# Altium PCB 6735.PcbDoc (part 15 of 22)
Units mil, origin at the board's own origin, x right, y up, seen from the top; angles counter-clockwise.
Board outline 2641.73 x 5165.35 mil, 6 copper layers (Top, Inner Layer 2, Inner Layer 3, Inner Layer 4, Inner Layer 5, Bottom), stack 35.7 mil thick; 1011 components, 790 nets, 4118 pads, 9325 vias.
Unrouted connection lines stored in the file: 4610.
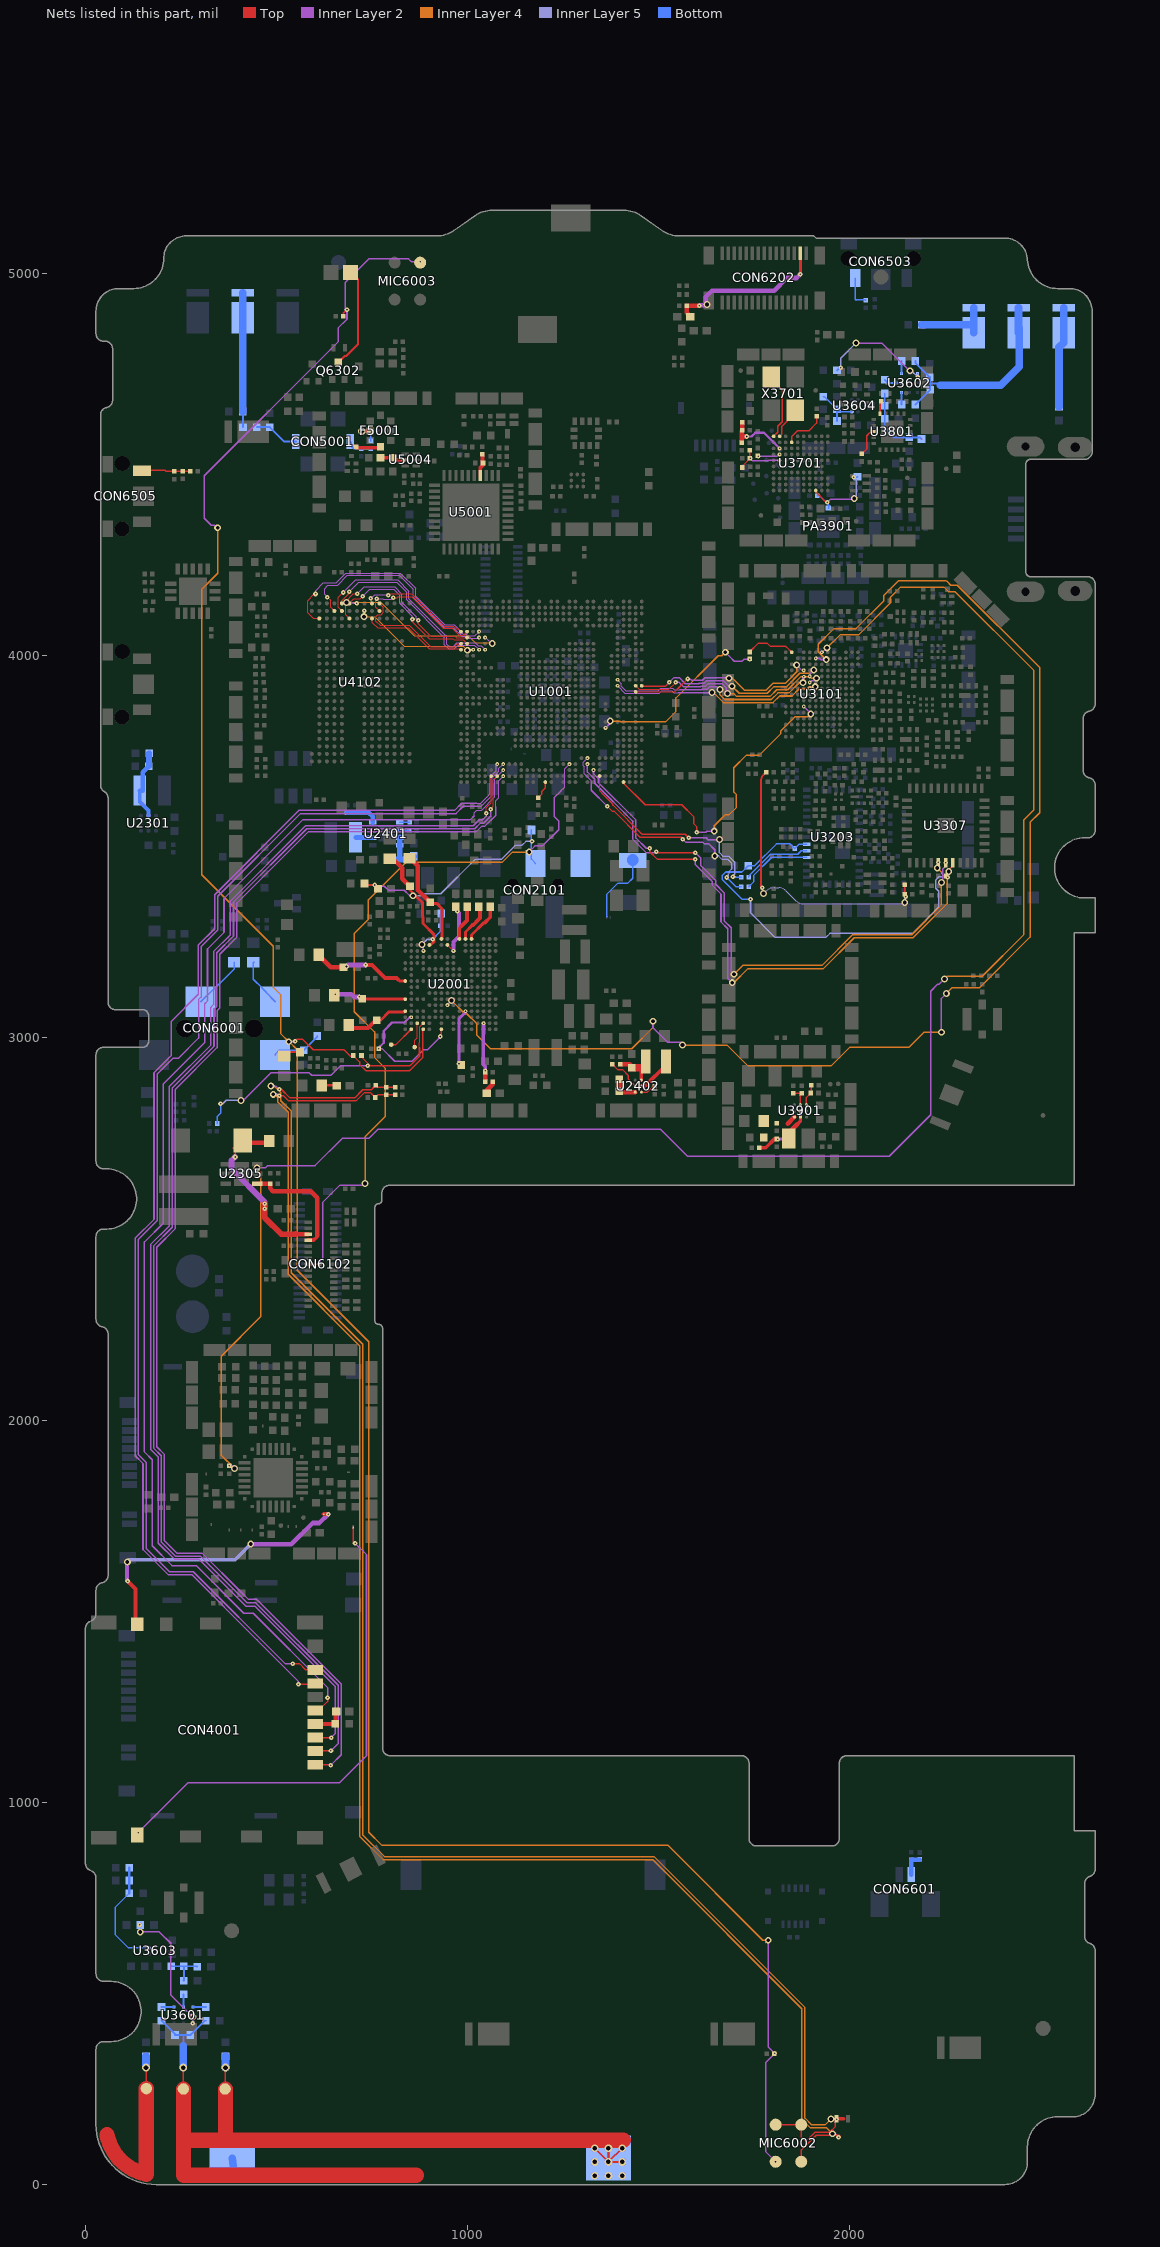
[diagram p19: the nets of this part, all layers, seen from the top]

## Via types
v1: diameter 12, hole 4, Top to Inner Layer 2, 3329 vias
v2: diameter 12, hole 4, Inner Layer 5 to Bottom, 3071 vias
v3: diameter 18, hole 10, Inner Layer 2 to Inner Layer 5, 1928 vias
v4: diameter 10, hole 4, Top to Inner Layer 2, 525 vias
v5: diameter 20, hole 12, Top to Bottom, 472 vias

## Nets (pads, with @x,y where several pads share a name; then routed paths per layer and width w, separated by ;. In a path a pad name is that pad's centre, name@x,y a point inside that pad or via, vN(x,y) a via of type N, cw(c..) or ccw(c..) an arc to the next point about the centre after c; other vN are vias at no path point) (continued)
LCM_LEDA: C2319.1 CON6102.3 D2301.2 | length 516.2
  Top w4: v1(391.35,2688.41) 391.35,2711.19 391.35,2731.15 D2301.2@411.31,2731.15 ; CON6102.3@581.19,2486.73 580.95,2486.97 CON6102.3@582.62,2486.73 581.31,2486.09 CON6102.3@581.95,2486.73
  Top w12: D2301.2@391.35,2711.19 D2301.2@411.31,2731.15 411.31,2725.89 476.53,2725.89 C2319.1@480.72,2730.09 ; 550.31,2486.73 581.19,2486.73 581.95,2486.73 CON6102.3@582.62,2486.73
  Top w15: v1(469.21,2553.49) v1@469.31,2553.49 ; v1(469.43,2565.59) 469.31,2565.59 v1@469.31,2553.49 ; 550.31,2486.73 549.67,2486.09 512.57,2486.09 469.31,2529.34 v1@469.31,2553.49
  Inner Layer 2 w15: v1(391.35,2688.41) 381.92,2678.98 381.92,2657.39 469.31,2570 v1@469.31,2567.09 ; v1(469.21,2553.49) 469.31,2554.79 v1@469.31,2567.09 ; v1(469.43,2565.59) v1@469.31,2567.09
LCM_LEDK: CON6102.4 R2310.1 U2305.1 | length 309
  Top w10: CON6102.4@582.62,2470.98 597.46,2470.98 606.31,2479.84 606.31,2481.91
  Top w12: U2305.1@449.29,2618.9 469.54,2618.9 469.95,2618.49 R2310.1@482.95,2618.49 482.95,2606.49 490.37,2599.07 589.44,2599.07 606.31,2582.2 606.31,2481.91
LCM_RST: CON6102.8 U1001.W4 | length 1910.4
  Top w4: CON6102.8@582.62,2407.99 599.34,2407.99 599.44,2408.09 v1(612.31,2408.09)
  Inner Layer 2 w3: 1243.95,3646.17 1253.45,3655.67 1253.45,3703.77 v4(1266.2,3716.51)
  Inner Layer 2 w4: v1(612.31,2408.09) 614.31,2408.09 614.31,2416.09 621.28,2423.06 621.28,2570.34 666.04,2615.09 731.65,2615.09 v3(731.65,2618.97) ; v3(1161.17,3486.23) 1161.17,3487.17 1169.5,3495.5 1177.1,3503.09 1196.49,3503.09 1238.31,3544.92 1238.31,3567.75 1225.95,3580.11 1225.95,3628.17 1243.95,3646.17
  Inner Layer 4 w4: v3(731.65,2618.97) 731.65,2741.43 783.95,2793.74 783.95,2921.07 756.31,2948.71 756.31,3015.72 703.31,3068.72 703.31,3273.08 739.31,3309.08 739.31,3360.3 838.1,3459.09 1089.83,3459.09 1116.97,3486.23 v3(1161.17,3486.23)
LTE_LTEX26M_IN: R1102.2 U3101.M1 | length 130.1
  Top w4: R1102.2@1738.15,4009.59 1738.15,4010.59 1760.64,4033.08 1783.37,4033.08 1791.13,4025.32 1830.81,4025.32 1833.54,4022.59 1834.15,4022.59 U3101.M1@1847.91,4008.83
LTE_RFIC0_BSI_CK: U1001.AG18 U3101.K6 | length 579.6
  Top w4: U3101.K6@1879.41,3930.09 1879.49,3930.09 1879.49,3944.92 v4(1879.58,3944.92)
  Inner Layer 2 w3: v4(1392.18,3936.99) 1402.07,3927.09 1402.07,3919.83 1413.34,3908.56 1498.78,3908.56 1504.81,3914.59 1536.45,3914.59 1540.46,3910.58 1555.02,3910.58 1555.27,3910.83
  Inner Layer 2 w4: 1555.27,3910.83 1611.86,3910.83 1612.64,3911.61 1625.68,3911.61 1632.66,3918.59 1652.51,3918.59 v3(1659.95,3911.15) ; v3(1877.14,3929.41) 1877.14,3942.49 v4(1879.58,3944.92)
  Inner Layer 4 w4: v3(1659.95,3911.15) 1659.95,3898.08 1672.62,3885.41 1794.45,3885.41 1811.62,3902.58 1840.68,3902.58 1867.51,3929.41 v3(1877.14,3929.41)
LTE_RFIC0_BSI_D0: U1001.AK17 U3101.J6 | length 558
  Top w3: U1001.AK17@1439.43,3921.24 1448.84,3911.81 1526.31,3911.81 1544.31,3929.81 v1(1544.31,3930.09)
  Inner Layer 2 w4: v1(1544.31,3930.09) 1553.69,3930.09 1564.95,3918.83 1608.51,3918.83 1609.3,3919.62 1622.1,3919.62 1629.07,3926.59 1665.73,3926.59 1676.68,3915.64 1676.68,3903.6 v3(1679.41,3900.88) ; v4(1895.16,3930.09) 1899.17,3934.1 1905.84,3934.1 v3(1912.68,3940.94)
  Inner Layer 4 w4: v3@1679.41,3900.83 1696.21,3900.83 1703.44,3893.61 1722.31,3893.61 1787.1,3893.59 1791.27,3893.6 1808.63,3910.96 1837.48,3910.96 1870.93,3944.41 1896.28,3944.41 1899.76,3940.94 v3(1912.68,3940.94)
LTE_RFIC0_BSI_D1: U1001.AL17 U3101.J5 | length 530.3
  Top w4: U1001.AL17@1455.17,3921.24 1455.17,3920.09 1517.31,3920.09 v1(1527.31,3930.09)
  Inner Layer 2 w4: v1(1527.31,3930.09) 1540.06,3942.83 1553.43,3942.83 1569.43,3926.83 1605.12,3926.83 1605.94,3927.65 1618.25,3927.65 1625.2,3934.59 1669.04,3934.59 1683.44,3920.19 v3(1691.68,3920.19) ; v4(1895.16,3945.83) 1895.16,3952.17 v3(1905.4,3962.41)
  Inner Layer 4 w4: v3(1691.68,3920.19) 1710.26,3901.61 1783.86,3901.61 1801.59,3919.34 1834.54,3919.34 1869.01,3953.81 1896.8,3953.81 v3(1905.4,3962.41)
LTE_RFIC0_BSI_D2: U1001.AK16 U3101.K4 | length 519.1
  Top w3: U1001.AK16@1439.43,3905.49 1541.71,3905.49 1548.31,3912.09
  Top w4: 1548.31,3912.09 v1(1575.31,3939.09)
  Inner Layer 2 w4: v1(1575.31,3939.09) 1575.31,3938.05 1583.31,3938.05 1586.2,3935.16 1602.47,3935.16 1603.01,3935.7 1613.87,3935.7 1620.77,3942.59 1682.25,3942.59 v3(1683.95,3940.89) ; v3(1860.81,3975.65) 1874.88,3961.58 v4(1879.41,3961.58)
  Inner Layer 4 w4: v3(1683.95,3940.89) 1682.65,3939.59 1694.12,3939.59 1724.1,3909.61 1780.5,3909.61 1799.05,3928.15 1831.2,3928.15 1860.81,3957.76 v3(1860.81,3975.65)
LTE_RFIC0_BSI_EN: U1001.AG17 U3101.J7 | length 574.6
  Inner Layer 2 w3: v4(1392.18,3921.24) 1411.05,3902.37 1501.59,3902.37 1507.81,3908.59 1533.97,3908.59 1539.73,3902.83 1551.62,3902.83
  Inner Layer 2 w4: 1551.62,3902.83 1615.21,3902.83 1615.98,3903.6 1621.86,3903.6 v3(1639.15,3903.59) ; v4(1895.16,3914.34) 1899.74,3918.92 v3@1909.4,3918.92
  Inner Layer 4 w4: v3(1639.15,3903.59) 1643.13,3903.59 1669.31,3877.41 1799.19,3877.41 1816.36,3894.58 1848.67,3894.58 1867.68,3913.59 1887.76,3913.59 1893.13,3918.96 v3(1909.43,3918.95) v3(1909.43,3918.95)
LTE_TXBPI: U1001.AH1 U3101.K10 | length 804.2
  Top w4: U1001.AH1@1407.93,3669.27 1407.93,3666.4 1464.44,3609.89 1560.26,3609.89 1590.95,3579.2 1590.95,3561.07 1598.95,3553.07 v1(1598.95,3537.88)
  Inner Layer 2 w4: v1(1598.95,3537.88) 1622.73,3537.88 1625.76,3540.9 v3(1645.12,3540.9) ; v4(1879.41,3867.09) 1879.31,3867 1898.19,3848.12 v3(1897.65,3847.59)
  Inner Layer 4 w4: v3(1645.12,3540.9) 1645.12,3555.09 1674.02,3583.99 1683.92,3583.99 1703.08,3603.15 1703.08,3636.64 1696.06,3643.66 1696.06,3706.74 1729.43,3740.11 1763.2,3740.11 1819.62,3796.53 1819.62,3803.4 1856.71,3840.49 1890.55,3840.49 v3(1897.65,3847.59)
LTE_VMIPI: C3241.1 C3340.2 R3278.2 U3203.7 U3307.7 | length 1142.8
  Top w4: C3340.2@2251.65,3423.59 2251.65,3420.59 v1(2255.65,3420.59) 2255.65,3436.69 2269.55,3450.59 U3307.7@2269.55,3458.15
  Inner Layer 2 w4: v1(2255.65,3420.59) 2255.65,3432.59 v3(2258.65,3435.59)
  Inner Layer 5 w4: v2(1740.02,3362.86) 1740.02,3327.51 1804.44,3263.09 1937.51,3263.09 1947.8,3273.38 2069.44,3273.38 2069.67,3273.61 2082.08,3273.61 2082.31,3273.38 2163.79,3273.38 2232.65,3342.24 2232.65,3383.47 2224.65,3391.47 2224.65,3412.8 2233.46,3421.61 2244.67,3421.61 v3(2258.65,3435.59)
  Bottom w4: R3278.2@1733.65,3450.59 R3278.2@1734.07,3450.59 ; v2(1740.02,3362.86) 1718.05,3362.86 1666.12,3414.8 1666.12,3424.74 1675.48,3434.1 1717.57,3434.1 R3278.2@1734.07,3450.59 ; U3203.7@1886.76,3506.89 1866.95,3506.89 C3241.1@1855.65,3495.59 1847.65,3503.59 1847.65,3504.08 1844.14,3507.59 1807.72,3507.59 1750.31,3450.17 1734.07,3450.17 R3278.2@1734.07,3450.59
LTE_VSRAM_EXT: C2412.1 L2402.2 R1011.1 U2402.C1 | length 157.9
  Top w10: U2402.C1@1454.19,2889.84 1454.19,2922.09 L2402.2@1454.19,2926.54 ; L2402.2@1454.19,2926.54 L2402.2@1465.74,2938.09 L2402.2@1454.19,2926.54
  Top w12: R1011.1@1399.31,2931.09 1424.31,2931.09 1429.31,2926.09 C2412.1@1429.31,2922.09
  Top w20: C2412.1@1429.31,2922.09 1454.19,2922.09 1465.74,2922.09 L2402.2@1465.74,2938.09
LTEX26M_IN: R1102.1 U1001.AE10 | length 500.3
  Top w4: U1001.AE10@1360.59,3811.09 v4(1360.69,3811) ; U1001.AE10@1360.59,3811.09 1360.31,3811.09 v4(1360.69,3811) ; U1001.AE10@1360.59,3811.09 v4(1360.69,3811) ; U1001.AE10@1360.59,3811.09 1360.77,3811.09 v4(1360.69,3811)
  Inner Layer 2 w4: v4(1360.69,3811) 1371.77,3822.09 1371.77,3829.34 1372.31,3829.88 v3(1373.08,3829.11) ; v3(1674.08,4009.11) 1685.26,3997.94 1685.26,3997.77 1697.44,3985.59 1717.65,3985.59 1722.65,3990.59 v1(1738.15,3990.59)
  Inner Layer 4 w4: v3(1373.08,3829.11) 1398.02,3829.11 1400.3,3826.83 1517.77,3826.83 1544.95,3854.01 1544.95,3889.67 1655.36,4000.08 1665.05,4000.08 v3(1674.08,4009.11)
MICBIAS0: C2042.1 C6012.1 C6038.1 MIC6002.1 MIC6003.1 U2001.N16 | length 6955.5
  Top w4: v1(548.31,2991.09) 553.31,2996.09 568.7,2996.09 595.96,2968.83 676.49,2968.83 693.83,2951.49 700.31,2951.49 C2042.1@700.31,2954.09 717.34,2937.06 717.34,2930.73 733.98,2914.09 847.64,2914.09 882.31,2948.77 882.31,3022.72 U2001.N16@884.09,3022.72 ; C6038.1@674.31,4888.09 674.31,4896.09 683.81,4905.59 v1(684.31,4905.09) ; MIC6003.1@875.78,5028.52 v1(875.78,5030.63) ; v1(1805.42,60.09) MIC6002.1@1805.85,59.66 ; C6012.1@1802.31,342.09 v1(1803.31,343.09) 1803.36,343.09 C6012.1@1802.31,342.09
  Inner Layer 2 w4: v3(345.95,4334.83) 345.09,4333.97 337.31,4341.75 336.66,4341.09 329.38,4341.09 310.95,4359.52 310.95,4470.99 637.31,4797.35 641.68,4801.72 ; v3(531.95,2989.83) 531.95,2990.46 548.31,2990.46 v1(548.31,2991.09) ; 637.34,4797.35 660.95,4820.96 660.95,4857.09 684.31,4880.45 v1(684.31,4905.09) 680.31,4905.09 680.31,4977.36 741.04,5038.09 845.31,5038.09 852.78,5030.63 v1(875.78,5030.63) ; v3(1786.31,639.09) 1786.31,505.09 1785.95,504.73 1785.95,360.45 v1(1803.31,343.09) 1780.31,320.09 1780.31,85.2 v1(1805.42,60.09)
  Inner Layer 4 w4: v3(345.95,4334.83) 345.95,4215.54 304.31,4173.9 304.31,3426.95 491.31,3239.95 491.31,3132.04 511.31,3112.04 511.31,3010.47 v3(531.95,2989.83) 532.73,2990.61 554.31,2969.02 554.31,2392.2 741.31,2205.2 741.31,921.46 774.69,888.09 1523.31,888.09 1772.31,639.09 v3(1786.31,639.09) v3@1780.47,633.25
MICBIAS1: C2044.1 R6011.2 U2001.N15 | length 762
  Top w3: 873.95,2973.87 873.95,2987.73 874.31,2988.09 874.31,3028.69 U2001.N15@884.09,3038.47
  Top w4: C2044.1@722.31,2954.09 723.31,2953.09 723.31,2949.09 v1@740.31,2932.09 ; v1(738.75,2927.09) 740.31,2927.09 v1@740.31,2932.09 ; 873.95,2973.87 873.95,2951.72 849.32,2927.09 745.31,2927.09 v1@740.31,2932.09
  Inner Layer 2 w4: v3(407.18,2835.9) 407.18,2837.18 413.37,2837.18 485.28,2909.09 585,2909.09 592,2902.09 642.2,2902.09 667.2,2927.09 v1(738.75,2927.09)
  Inner Layer 5 w4: v2(353.38,2827.79) 359.01,2827.79 368.4,2837.18 399.11,2837.18 v3(407.18,2835.9)
  Bottom w4: R6011.2@344.31,2776.09 344.31,2793.85 353.38,2802.92 v2(353.38,2827.79)
MIPI0_SCLK: R3209.2 U1001.AD2 | length 553.9
  Top w3: U1001.AD2@1344.94,3685.02 1344.94,3646.55 1350.6,3640.88
  Top w4: 1350.6,3640.88 1380.02,3611.46 1380.02,3609.1 1456.05,3533.07 1569.12,3533.07 v1(1578.67,3523.53)
  Inner Layer 2 w4: v1(1578.67,3523.53) 1624.27,3523.53 1629.09,3518.7 v3(1658.63,3518.7)
  Inner Layer 5 w4: v3(1658.63,3518.7) 1658.63,3485.13 1668.35,3475.41 1683.64,3475.41 1698.46,3460.59 1698.46,3428.57 1692.81,3422.92 v2(1694.12,3421.6)
  Bottom w4: v2(1694.12,3421.6) 1695.01,3420.71 1704.58,3420.71 1704.7,3420.59 R3209.2@1715.65,3420.59
MIPI0_SCLK_PA: R3209.1 U3203.6 | length 181.6
  Bottom w4: R3209.1@1735.65,3420.59 1735.65,3423.85 1791.39,3479.59 1792.32,3480.5 1834.97,3480.5 1835.06,3480.59 1863.54,3480.59 1872.51,3489.57 U3203.6@1886.76,3489.57
MIPI0_SDATA: R3210.2 U1001.AB5 | length 647.6
  Top w4: v1(1365.66,3605.78) 1378.96,3592.48 1383.81,3592.48 1451.23,3525.06 1559.41,3525.06 1564.29,3520.18 v1(1562.66,3520.18)
  Inner Layer 2 w3: v4(1313.44,3732.26) 1302.94,3721.76 1302.94,3711.99 1305.45,3709.48 1305.45,3690.9 1323.4,3672.95 1323.4,3670.19
  Inner Layer 2 w4: 1323.4,3670.19 1323.4,3648.03 v1(1365.66,3605.78) ; v1(1562.66,3520.18) 1571.32,3511.52 1583.82,3511.52 1584.79,3512.49 1614.4,3512.49 1618.5,3508.39 1630.18,3508.39 1646.35,3492.22 v3(1646.35,3476.2)
  Inner Layer 5 w4: v3(1646.35,3476.2) 1656.25,3476.2 1665.36,3467.09 1680.65,3467.09 1690.46,3457.28 1690.46,3441.94 1684.88,3436.36 1684.88,3431.74 1681.8,3428.66 1681.8,3425.37 1677.16,3420.72 v2(1678.12,3419.77)
  Bottom w4: v2(1678.12,3419.77) 1702.27,3395.59 R3210.2@1715.65,3395.59
MIPI0_SDATA_PA: R3210.1 U3203.5 | length 193
  Bottom w4: R3210.1@1735.65,3395.59 1748.15,3408.09 1748.15,3425.02 1795.63,3472.5 1886.5,3472.5 U3203.5@1886.76,3472.24
MIPI1_SCLK: U1001.AC3 U3307.5 | length 1539.7
  Top w4: v1(1476.22,3496.09) 1476.22,3487.31 1495.7,3467.83 v1(1594.95,3467.83) ; v1(2231.65,3459.59) 2231.76,3459.49 U3307.5@2231.76,3458.15
  Inner Layer 2 w4: v4(1329.19,3700.77) 1329.19,3691.65 1341.31,3679.53 1341.31,3668.84 1440.31,3569.84 1440.31,3522.77 1466.99,3496.09 v1(1476.22,3496.09) ; v1(1594.95,3467.83) 1594.95,3454.42 1639.51,3409.86 1639.51,3399.77 1662.79,3376.48 1662.79,3303.36 1680.69,3285.46 1680.69,3156.17 v3(1692.32,3144.54) ; v3(2228.65,3444.59) 2231.65,3447.59 v1(2231.65,3459.59)
  Inner Layer 4 w4: v3(1692.32,3144.54) 1696.33,3144.54 1733.35,3181.56 1930.73,3181.56 2011.17,3262 2164.97,3262 2254.65,3351.69 2254.65,3415.59 2240.04,3430.2 2240.04,3433.2 v3(2228.65,3444.59)
MIPI1_SDATA: U1001.AB4 U3307.6 | length 1524
  Top w4: v1(1493.78,3486.72) 1492.82,3485.77 1493.79,3484.8 v1(1594.95,3484.8) ; U3307.6@2250.65,3458.15 v1(2250.65,3458.59) ; U1001.AB4@1313.21,3716.74 v4(1313.44,3716.51) 1313.44,3716.97 U1001.AB4@1313.21,3716.74
  Inner Layer 2 w4: v4(1313.44,3716.51) 1313.44,3695.59 1332.31,3676.72 1332.31,3666.09 1432.31,3566.09 1432.31,3519.46 1467.68,3484.09 1491.14,3484.09 v1(1493.78,3486.72) ; v1(1594.95,3484.8) 1595.29,3485.14 1609.31,3471.12 1609.31,3451.55 1648.83,3412.03 1648.83,3401.79 1670.79,3379.83 1670.79,3306.67 1689.33,3288.13 1689.33,3202.98 1689.09,3202.74 1689.09,3190.32 1689.33,3190.08 1689.33,3173.5 1695.7,3167.13 1696.95,3167.13 v3(1696.95,3166.56) ; v3(2239.65,3406.59) 2243.54,3410.48 2243.54,3442.48 2250.65,3449.59 v1(2250.65,3458.59)
  Inner Layer 4 w4: v3(1696.95,3166.56) 1719.95,3189.56 1926.71,3189.56 2007.15,3270 2161.65,3270 2239.65,3348 v3(2239.65,3406.59)
MIPI_VRT: R1227.1 U1001.R1 | length 48
  Top w4: R1227.1@1184.95,3628.83 1193.24,3637.12 1193.24,3644.19 1203.2,3654.15 U1001.R1@1203.2,3669.27
MSDC0_CLK: U1001.C23 U4102.B8 | length 338
  Inner Layer 2 w3: v3(728.77,4102.14) 728.77,4115.97 v1(729.92,4117.11) ; v3(999.08,4014.11) 1000.69,4015.72 v4(1014.23,4015.73)
  Inner Layer 4 w3: v3(728.77,4102.14) 756.72,4102.14 834.25,4024.61 988.58,4024.61 v3(999.08,4014.11)
MSDC0_CMD: U1001.B24 U4102.A6 | length 404
  Top w3: U4102.A6@690.56,4136.8 702.42,4148.67 718.68,4148.67 v1(725.36,4155.35) ; v1(855.58,4094.86) 855.58,4088.86 899.83,4044.61 961.33,4044.61 964.86,4041.08 988.87,4041.08 U1001.B24@998.48,4031.47
  Inner Layer 2 w3: v1(725.36,4155.35) 744.29,4174.28 806.68,4174.28 822.15,4158.81 822.15,4136.72 855.58,4103.29 v1(855.58,4094.86)
MSDC0_DAT0: U1001.A26 U4102.A9 | length 298.3
  Top w3: v1(746.76,4149.89) 749.61,4147.03 U4102.A9@749.61,4136.8 ; v1(791.8,4157.78) 796.49,4162.47 853.22,4162.47 938.08,4077.61 962.83,4077.61 970.32,4070.11 975.58,4070.11 U1001.A26@982.73,4062.97
  Inner Layer 2 w3: v1(746.76,4149.89) 756.66,4159.79 789.78,4159.79 v1(791.8,4157.78)
MSDC0_DAT1: U1001.B26 U4102.B10 | length 323.7
  Top w3: v1(761.8,4149.29) 759.48,4146.97 759.48,4126.93 U4102.B10@769.3,4117.12 ; v1@806.3,4152.61 v1(805.65,4151.97) 815.59,4151.97 817.71,4154.09 853.12,4154.09 934.69,4072.52 934.8,4072.52 935.71,4071.61 959.63,4071.61 977.7,4053.55 989.06,4053.55 U1001.B26@998.48,4062.97
  Inner Layer 2 w3: v1(761.8,4149.29) 777.37,4149.29 779.38,4147.28 799.74,4147.28 v1(805.65,4151.97)
MSDC0_DAT2: U1001.B25 U4102.C6 | length 457.9
  Top w3: U4102.C6@690.56,4097.43 680.73,4107.25 680.73,4141.49 701.08,4161.84 v1(711.5,4161.84) ; v1(870.58,4092.22) 870.58,4083.37 903.34,4050.61 967.07,4050.61 970.45,4047.22 U1001.B25@998.48,4047.22
  Inner Layer 2 w3: v1(711.5,4161.84) 729.93,4180.28 809.17,4180.28 828.15,4161.29 828.15,4140.15 866.08,4102.22 866.08,4096.72 v1(870.58,4092.22)
MSDC0_DAT3: U1001.E23 U4102.B5 | length 549.9
  Top w3: U4102.B5@670.87,4117.12 661.05,4126.93 661.05,4152.32 v1(674.14,4165.42)
  Inner Layer 2 w3: v1(674.14,4165.42) 674.14,4165.86 706.55,4198.28 816.62,4198.28 846.15,4168.75 846.15,4148.47 945.62,4049 945.62,4030.47 952.48,4023.61 961.79,4023.61 971.79,4033.61 1020.09,4033.61 1027.48,4026.22 1035.22,4026.22 v4(1045.72,4015.73)
MSDC0_DAT4: U1001.A23 U4102.C9 | length 272.4
  Top w3: U4102.C9@749.61,4097.43 749.61,4088.11 764.61,4073.11 844.33,4073.11 899.83,4017.61 980.85,4017.61 U1001.A23@982.73,4015.73
MSDC0_DAT5: U1001.A24 U4102.A10 | length 316.9
  Top w3: U4102.A10@769.3,4136.8 779.11,4126.98 779.11,4113.05 773.34,4107.28 765.26,4107.28 759.47,4101.49 759.47,4090.47 770.83,4079.11 847.33,4079.11 902.83,4023.61 965.83,4023.61 973.33,4031.11 U1001.A24@982.33,4031.11
MSDC0_DAT6: U1001.D23 U4102.A5 | length 492.9
  Top w3: U4102.A5@670.87,4136.8 670.87,4143.7 690.38,4163.22 v1(690.38,4167.26)
  Inner Layer 2 w3: v1(690.38,4167.26) 715.4,4192.28 814.14,4192.28 840.15,4166.26 840.15,4145.99 938.91,4047.23 938.91,4028.69 950,4017.61 964.88,4017.61 974.88,4027.61 1017.61,4027.61 1025,4020.22 1029.74,4015.48 v4(1029.98,4015.73)
MSDC0_DAT7: U1001.D25 U4102.B4 | length 568.4
  Top w3: v1(633.14,4153.03) 641.37,4144.8 641.37,4126.93 U4102.B4@651.19,4117.12
  Inner Layer 2 w3: v1(633.14,4153.03) 625.52,4160.64 625.52,4175.77 634.15,4184.4 659.52,4184.4 685.4,4210.28 821.59,4210.28 858.15,4173.72 858.15,4153.44 938.49,4073.11 962.7,4073.11 985.2,4050.61 992.83,4050.61 997.33,4046.11 1028.87,4046.11 v4(1029.98,4047.22)
MSDC0_DSL: U1001.E25 U4102.A7 | length 483.7
  Inner Layer 2 w3: v3(682.6,4139.38) 696.63,4139.38 699.21,4136.8 v1(710.24,4136.8) ; v4(1045.72,4047.22) 1046.97,4047.22 1061.95,4032.24 1064.31,4032.24 v3(1064.31,4032.09)
  Inner Layer 4 w3: v3(682.6,4139.38) 772.83,4139.38 860.31,4051.9 1001.49,4051.9 1019.28,4034.11 1064.08,4034.11 1064.11,4032.92 1064.45,4032.86 1065.32,4032.71 1065.91,4032.59 1066.04,4032.57 v3(1064.31,4032.09)
MSDC0_RSTB: U1001.D26 U4102.C2 | length 636.9
  Top w3: v1(601.95,4161.49) 598.92,4161.49 580.95,4143.52 580.95,4112.49 595.94,4097.5 U4102.C2@611.82,4097.43
  Inner Layer 2 w3: v1(601.95,4161.49) 601.95,4170.49 621.86,4190.4 655.66,4190.4 681.54,4216.28 824.1,4216.28 864.15,4176.22 864.15,4155.93 939.47,4080.61 964.33,4080.61 988.33,4056.61 995.83,4056.61 1000.33,4052.11 1019.12,4052.11 v4(1029.98,4062.97)
MSDC1_CLK: CON4001.5 U1001.H3 | length 3384.4
  Top w4: CON4001.5@601.19,1240.23 610,1240.23 633.31,1263.55 v1(633.31,1273.09)
  Inner Layer 2 w3: 1017.31,3581.26 1017.31,3589.09 1024.31,3596.09 1036.31,3596.09 1070.94,3630.72 1070.94,3677.95 1093.36,3700.37 v4(1092.97,3700.77) v4@1090.95,3698.75
  Inner Layer 2 w4: v1(633.31,1273.09) 633.31,1300.37 438.92,1494.76 414.44,1494.76 289.62,1619.58 226.36,1619.58 174.51,1671.43 174.51,1896.5 154.31,1916.7 154.31,2465.99 203.31,2514.99 203.31,2879.46 312.03,2988.18 312.03,3089.44 319.31,3096.72 319.31,3232.84 362.46,3275.99 362.46,3364.45 569.11,3571.09 1007.14,3571.09 1017.31,3581.26
MSDC1_CMD: CON4001.3 U1001.F2 | length 3446.3
  Top w3: v1(1048.17,3587.63) 1048.17,3602.38 1061.47,3615.68 U1001.F2@1061.47,3685.02
  Top w4: CON4001.3@601.19,1169.37 602.91,1171.09 607.31,1171.09 609.31,1169.09 v1(642.6,1169.09)
  Inner Layer 2 w4: v1(642.6,1169.09) 653.31,1179.8 653.31,1302.99 443.44,1512.87 420.3,1512.87 297.34,1635.83 232.73,1635.83 190.51,1678.05 190.51,1903.31 170.31,1923.51 170.31,2459.17 219.31,2508.17 219.31,2872.62 328.12,2981.43 328.12,3080.35 335.31,3087.54 335.31,3226.13 379.2,3270.02 379.2,3358.55 575.73,3555.09 1014.81,3555.09 1030.3,3570.58 1039.12,3570.58 1048.17,3579.63 v1(1048.17,3587.63)
MSDC1_DAT0: CON4001.7 U1001.G4 | length 3324.8
  Top w4: v1(557.31,1309.09) 599.18,1309.09 CON4001.7@601.19,1311.1
  Inner Layer 2 w3: 1023.31,3614.09 1033.73,3614.09 1058.52,3638.88 1058.52,3682.93 1074.95,3699.36 1074.95,3714.24 v4(1077.22,3716.51)
  Inner Layer 2 w4: v1(557.31,1309.09) 557.31,1316.37 448.8,1424.88 278.52,1595.17 245.39,1595.17 245.31,1595.09 216.91,1595.09 150.51,1661.48 150.51,1886.29 130.31,1906.49 130.31,2476.22 179.31,2525.22 179.31,2909.09 224.22,2954 224.22,3029.61 224.31,3029.71 224.31,3043.09 295.31,3114.09 295.31,3242.84 338,3285.53 338,3374.77 558.33,3595.09 965.31,3595.09 984.31,3614.09 1023.31,3614.09
MSDC1_DAT1: CON4001.8 U1001.H4 | length 3306.1
  Top w4: v1(542.31,1363.09) 559.68,1363.09 576.23,1346.53 CON4001.8@601.19,1346.53 ; v4(1092.97,3716.51) 1093.93,3716.51 v4(1092.97,3716.51)
  Inner Layer 2 w3: 1027.31,3606.09 1035.31,3606.09 1064.61,3635.39 1064.61,3680.21 1081.95,3697.55 1081.95,3705.49 v4(1092.97,3716.51)
  Inner Layer 2 w4: v1(542.31,1363.09) 522.41,1363.09 282.18,1603.31 220,1603.31 158.51,1664.8 158.51,1889.69 138.31,1909.89 138.31,2472.81 187.31,2521.81 187.31,2905.09 229.23,2947 243.31,2947 295.8,2999.49 295.8,3100.46 303.31,3107.97 303.31,3239.52 346.15,3282.36 346.15,3370.76 562.48,3587.09 969.63,3587.09 988.63,3606.09 1027.31,3606.09
MSDC1_DAT2: CON4001.1 U1001.H2 | length 3536.3
  Top w4: v1@643.22,1097.49 v1(642.23,1097.49) 641.22,1098.5 CON4001.1@601.19,1098.5 ; CON4001.1@601.19,1098.5 603.19,1096.49 CON4001.1@601.19,1098.5
  Inner Layer 2 w3: 1073.31,3604.27 1073.31,3621.09 1081.06,3628.84 1081.06,3673.1 v4(1092.97,3685.02)
  Inner Layer 2 w4: v1(642.23,1097.49) 669.31,1124.57 669.31,1309.63 448.11,1530.83 426.48,1530.83 406.22,1551.09 305.23,1652.09 239.1,1652.09 206.51,1684.68 206.51,1910.13 186.31,1930.33 186.31,2452.34 235.31,2501.34 235.31,2865.95 344.31,2974.95 344.31,3071.33 351.31,3078.33 351.31,3219.15 396.31,3264.15 396.31,3353.04 582.36,3539.09 1022.14,3539.09 1037.14,3554.09 1045.26,3554.09 1073.31,3582.15 1073.31,3604.27
MSDC1_DAT3: CON4001.2 U1001.G2 | length 3487.8
  Top w3: v1@1059.95,3598.28 v1(1060.24,3598.28) 1067.47,3605.51 1067.47,3675.27 U1001.G2@1077.22,3685.02
  Top w4: CON4001.2@601.19,1133.93 CON4001.2@602.34,1135.09 ; CON4001.2@603.74,1136.49 CON4001.2@602.34,1135.09 ; v1(642.31,1135.09) CON4001.2@602.34,1135.09
  Inner Layer 2 w4: v1(642.31,1135.09) 661.31,1154.09 661.31,1306.31 445.77,1521.85 423.39,1521.85 301.28,1643.96 235.92,1643.96 198.51,1681.37 198.51,1906.72 178.31,1926.92 178.31,2455.76 227.31,2504.76 227.31,2869.28 336.31,2978.28 336.31,3075.94 343.31,3082.94 343.31,3222.64 387.31,3266.64 387.31,3355.36 579.05,3547.09 1018.48,3547.09 1033.48,3562.09 1041.94,3562.09 1060.24,3580.38 v1(1060.24,3598.28)
MSDC_NFC_SWPIO: CON4001.9 SH5108.1 | length 1299.7
  Top w4: CON4001.9@135.64,914.44 135.63,918.51 v1(137.95,920.83) ; SH5108.1@700.31,1719.09 700.31,1683.09 v1(705.31,1678.09)
  Inner Layer 2 w4: v1(137.95,920.83) 267.75,1050.63 664.15,1050.63 735.31,1121.79 735.31,1648.09 v1(705.31,1678.09)
MSDC_NFC_VCCSWP: CON4001.10 SH5107.1 | length 765.6
  Top w10: v1(110.15,1579.03) 131.31,1557.87 131.31,1469.94 CON4001.10@135.64,1465.63 ; SH5107.1@623.3,1754.09 634.38,1754.09 v1(634.78,1753.69)
  Inner Layer 2 w10: v3(109.54,1629.06) 108.31,1629.06 108.31,1579.03 v1(110.15,1579.03)
  Inner Layer 2 w12: v3(432.34,1675.49) 538.84,1675.49 594.18,1730.83 611.93,1730.83 v1(634.78,1753.69)
  Inner Layer 5 w10: v3(109.54,1629.06) 115.31,1634.83 391.68,1634.83 v3(432.34,1675.49)
MT6169_XO3_CLK: R5130.1 U3101.G1 | length 4799.5
  Inner Layer 2 w4: v1(376.31,1880.09) 384.31,1880.09 390.31,1874.09 v3(390.31,1873.09) ; v3(448.55,2660.09) 470.8,2660.09 476.8,2666.09 600.91,2666.09 671.91,2737.09 741.22,2737.09 765.22,2761.09 1504.31,2761.09 1574.84,2690.56 2102.99,2690.56 2211.31,2798.88 2211.31,3122.15 2229.34,3140.17 2233.4,3140.17 v3(2247.31,3154.09) ; v4(1926.65,4008.83) 1927.14,4008.34 1939.88,4021.08 v3(1940.36,4020.59)
  Inner Layer 4 w4: v3(390.31,1873.09) 355.31,1908.09 355.31,2167.4 458.31,2270.4 458.31,2650.32 v3(448.55,2660.09) ; v3(1940.36,4020.59) 1974.27,4054.5 2022.27,4054.5 2106.06,4138.3 2106.06,4152.8 2132.77,4179.5 2246.18,4179.5 2247.18,4178.5 2247.28,4178.5 2258.21,4167.57 2275.33,4167.57 2480.65,3962.24 2480.65,3595.93 2455.4,3570.68 2455.4,3437.62 ; v3(2247.31,3154.09) 2254.31,3161.09 2346.15,3161.09 2455.43,3270.37 2455.43,3376.38 ; 2455.41,3376.4 2455.41,3437.61
MT6169_XO4_CLK: U2001.J12 U3101.H2 | length 3437.5
  Inner Layer 2 w4: v4(947.08,3085.71) 946.58,3086.22 957.95,3097.58 v3(957.44,3098.09) ; v3(1484.72,3043.56) 1484.72,3026.83 1523.46,2988.09 1558.31,2988.09 1562.26,2987.91 1562.31,2987.23 v3(1562.3,2981.36) ; v4(1910.9,3993.08) 1920.79,3993.08 1924.28,3989.59 v3(1938.16,3989.59) ; v3(2239.38,3014.91) 2239.38,3103.15 v3(2252.31,3116.09)
  Inner Layer 4 w4: v3(957.44,3098.09) 992.37,3063.16 997.84,3063.16 1024.13,3036.86 1024.13,3007.14 1059.44,2971.83 1429.27,2971.83 1484.72,3027.29 v3(1484.72,3043.56) ; v3(1562.3,2981.36) 1678.78,2981.36 1733.57,2926.56 1950.73,2926.56 1999.26,2975.09 2153.99,2975.09 2193.81,3014.91 v3(2239.38,3014.91) ; v3(1938.16,3989.59) 1917.36,4010.38 1917.36,4030.12 1958.17,4070.92 2016.06,4070.92 2089.06,4143.92 2089.06,4158.42 2126.29,4195.65 2252.65,4195.65 2253.8,4194.5 2253.9,4194.5 2263.86,4184.54 2280.98,4184.54 2496.65,3968.87 2496.65,3589.3 2471.4,3564.05 2471.4,3465.98 2471.41,3383.09 ; v3(2252.31,3116.09) 2267.31,3131.09 2338.78,3131.09 2471.43,3263.74 2471.43,3383.07
N814026: CON6001.5 R6002.2 R6005.1 | length 133.1
  Bottom w4: CON6001.5@496.24,2954.83 498.24,2959.09 506.64,2967.49 R6005.1@570.95,2967.49 606.31,3002.85 R6002.2@606.31,3005.09
N814140: BEAD6003.2 CON6001.4 | length 129.6
  Bottom w4: BEAD6003.2@438.95,3197.9 440.95,3197.9 438.95,3195.9 438.95,3153.37 449.36,3142.96 449.87,3142.96 CON6001.4@496.24,3094.59
N814198: BEAD6005.2 CON6001.3 | length 140.5
  Bottom w4: CON6001.3@301.36,3094.59 364.89,3156.12 365.38,3156.12 388.95,3179.69 BEAD6005.2@388.95,3197.9
N814232: BEAD6002.1 R6003.2 | length 53.6
  Top w4: R6003.2@559.57,2964.83 561.31,2963.09 R6003.2@561.31,2962.09
  Top w6: BEAD6002.1@519.95,2952.42 519.95,2959.83 523.21,2963.09 R6003.2@561.31,2963.09
N814252: BEAD6004.1 R6004.2 | length 39.4
  Top w6: BEAD6004.1@618.54,2875.83 655.95,2875.83 655.95,2874.83 R6004.2@656.95,2874.83
N816374: C6013.2 C6016.1 MIC6002.4 R6023.1 | length 4284.9
  Top w4: v1(506.95,2848.83) 517.85,2848.83 531.59,2835.09 707.95,2835.09 728.95,2856.09 746.8,2856.09 750.31,2852.57 750.31,2852.09 C6016.1@758.31,2844.09 765.31,2851.09 C6013.2@787.31,2851.09 R6023.1@810.31,2851.09 ; MIC6002.4@1872.78,59.66 1872.78,90.09 1911.78,129.09 1973.31,129.09 1973.31,122.81 1972.03,124.09 v1(1970.31,124.09)
  Inner Layer 2 w4: v3(491.46,2852.38) 503.4,2852.38 v1(506.95,2848.83) ; v3(1954.94,132.75) 1961.66,132.75 v1(1970.31,124.09)
  Inner Layer 4 w4: v3(491.46,2852.38) 495.41,2852.38 503.14,2844.65 503.14,2832.41 530.31,2805.24 530.31,2381.85 717.31,2194.85 717.31,911.52 778.75,850.09 1483.94,850.09 1874.31,459.71 1874.31,170.78 1897,148.09 1939.6,148.09 v3(1954.94,132.75)
N816382: C6013.1 C6015.1 MIC6002.2 MIC6002.3 R6024.1 SH6003.1 | length 4382.3
  Top w4: v1(506.95,2865.83) 506.76,2865.64 512.35,2865.64 534.9,2843.09 704.58,2843.09 725.58,2864.09 747.8,2864.09 751.61,2867.89 751.61,2868.38 C6015.1@759.31,2876.09 764.31,2871.09 C6013.1@787.31,2871.09 R6024.1@810.31,2871.09 ; MIC6002.2@1805.85,156.52 MIC6002.3@1872.78,156.52 1872.78,123.63 1881.31,115.09 1886.46,115.09 1908.46,137.09 1947.31,137.09 1962.31,152.09 1962.31,169.09 SH6003.1@1965.31,172.09 v1(1965.31,171.09)
  Inner Layer 2 w4: v3(484.96,2874.09) 498.69,2874.09 v1(506.95,2865.83) ; v3(1950.25,171.71) 1950.31,171.65 1950.31,170.09 1951.31,171.09 v1(1965.31,171.09)
  Inner Layer 4 w4: v3(484.96,2874.09) 484.96,2872.09 495.96,2872.09 511.14,2856.9 511.14,2835.72 538.31,2808.55 538.31,2385.3 725.31,2198.3 725.31,914.83 782.06,858.09 1487.26,858.09 1882.31,463.03 1882.31,174.09 1900.31,156.09 1934.63,156.09 v3(1950.25,171.71)
N15601288: R2041.2 U2001.F1 | length 111.5
  Top w8: U2001.F1@994.32,3258.94 994.32,3270.2 994.32,3277.2 1012.95,3295.83
  Top w10: 1012.95,3295.83 1014.46,3295.83 1028.31,3309.7 1028.31,3309.92 1032.31,3313.92 1032.31,3341.83 R2041.2@1028.95,3341.83 ; R2041.2@1023.95,3341.83 R2041.2@1028.45,3341.83 ; R2041.2@1028.95,3342.83 R2041.2@1028.45,3341.83 ; R2041.2@1028.45,3341.83 1027.95,3340.83 R2041.2@1028.95,3341.83 ; R2041.2@1028.45,3341.83 R2041.2@1028.95,3341.83
N15601296: R2040.2 U2001.E1 | length 105.6
  Top w8: U2001.E1@1010.07,3258.94 1010.07,3269.4 1041.76,3301.09 1044.31,3301.09
  Top w10: 1044.31,3301.09 1058.95,3315.73 R2040.2@1058.95,3342.83
N15601786: R2046.2 U2001.G1 | length 102
  Top w4: R2046.2@993.59,3342.23 998.55,3342.23 998.95,3341.83 R2046.2@998.95,3342.83
  Top w8: U2001.G1@978.57,3258.94 978.57,3273.88 978.57,3287.45 982.95,3291.83
  Top w10: 982.95,3291.83 997.95,3306.83 997.95,3336.83 R2046.2@998.95,3341.83 ; R2046.2@995.95,3341.83 R2046.2@998.95,3341.83 ; R2046.2@997.95,3340.83 R2046.2@998.95,3341.83
N15603707: TP2016.1 U2001.P15 | length 65.3
  Top w3: TP2016.1@861.31,2976.09 861.31,2993.74 868.31,3000.74 868.31,3031.6 ; 868.34,3031.63 U2001.P15@868.34,3038.47
N15603711: TP2015.1 U2001.R16 | length 69.3
  Top w4: TP2015.1@800,2982.5 812.37,2982.5 U2001.R16@852.59,3022.72
N15605292: C2027.1 U2001.F13 | length 153.4
  Top w4: v1(977.31,2932.49) 977.96,2933.14 982.66,2928.44 982.66,2929.09 C2027.1@983.31,2929.09
  Inner Layer 2 w8: v1(977.31,2932.49) 977.31,3050.24 994.32,3067.25 v4(994.32,3069.96)
N15606290: C2036.1 U2001.K16 U2001.R14 | length 367
  Top w4: C2036.1@766.31,2973.09 v1(767.31,2972.09) ; v1(928.21,3003.66) 930.3,3008.09 v1@931.3,3008.09 ; v1@931.33,3008.11 U2001.K16@931.33,3022.72 ; U2001.K16@932.3,3022.09 U2001.K16@931.67,3022.72 ; U2001.K16@931.33,3022.72 U2001.K16@931.67,3022.72 ; U2001.K16@931.33,3022.72 U2001.K16@931.67,3022.72
  Inner Layer 2 w4: v1@765.31,2972.09 v1(767.31,2972.09) 776.16,2972.09 809.16,2939.09 854.17,2939.09 884.17,2969.09 894.85,2969.09 928.21,3002.45 v1(928.21,3003.66)
  Inner Layer 2 w6: v1@765.31,2972.09 780.31,2987.09 780.31,3018.09 802.31,3040.09 834.31,3040.09 848.44,3054.22 v4(852.59,3054.22)
N15921668: ANT3605.1 ANT3605.2 R3622.1 | length 263.7
  Bottom w20: R3622.1@2546.95,4651.49 2546.95,4806.73 2559.31,4819.09 ANT3605.2@2559.31,4845.13 ANT3605.1@2559.31,4910.09
N15925478: ANT3604.1 ANT3604.2 L3602.1 L3608.2 R3606.2 R3611.1 R3614.1 | length 583.8
  Bottom w5: R3606.2@2171.3,4657.09 L3602.1@2210.3,4696.09 2210.3,4712.09 ; L3608.2@2171.3,4771.09 2171.3,4767.09 2209.3,4729.09 R3614.1@2209.3,4728.09 2210.3,4728.09 2210.3,4712.09 ; 2236.3,4708.09 2236.3,4712.09 2210.3,4712.09
  Bottom w19.69: 2236.3,4708.09 2395.3,4708.09 2443.3,4756.09 2443.3,4793.09
  Bottom w20: ANT3604.1@2441.31,4910.09 ANT3604.2@2441.31,4845.13 2443.3,4858.05 2443.3,4793.09
N16931615: ANT5003.1 ANT5003.2 C5003.1 R5004.1 | length 359.8
  Bottom w4: C5003.1@410.96,4647.09 410.96,4639.09 C5003.1@411.31,4639.09
  Bottom w5: C5003.1@411.31,4639.09 412.31,4638.09 R5004.1@412.31,4598.09
  Bottom w20: C5003.1@411.31,4639.09 ANT5003.2@411.31,4884.13 ANT5003.1@411.31,4949.09
N16931617: CON5001.2 L5011.1 R5005.1 | length 66.8
  Bottom w5: CON5001.2@692.17,4560.09 695.31,4556.95 695.31,4548.09 701.31,4542.09 L5011.1@721.31,4542.09 R5005.1@746.31,4542.09
N16931618: CON5001.1 L5004.1 R5004.2 | length 117.9
  Bottom w5: R5004.2@448.31,4598.09 L5004.1@482.31,4598.09 520.31,4560.09 CON5001.1@550.43,4560.09
N16931625: F5001.2 L5012.1 R5005.2 | length 71.1
  Top w10: v5(723.31,4587.09) 745.38,4587.09 F5001.2@745.38,4588.11
  Bottom w5: v5(723.31,4587.09) L5012.1@746.31,4587.09 R5005.2@746.31,4562.09
N16931626: C5004.1 F5001.4 | length 69.6
  Top w10: C5004.1@708.08,4547.11 708.08,4544.09 771.95,4544.09 F5001.4@771.95,4546.77
N17415034: L5010.1 R5016.2 U5001.34 | length 60.2
  Top w10: U5001.34@1032.7,4471.17 1032.7,4491.53 1040.08,4498.91 L5010.1@1040.08,4504.11 1039.1,4505.09 1039.1,4527.09 R5016.2@1038.31,4527.09
N17416996: C5017.1 L5003.2 U5004.5 | length 67.7
  Top w10: L5003.2@772.08,4518.11 C5017.1@804.08,4518.11 810.08,4512.11 U5004.5@837.3,4512.11
N17645327: C6601.1 CON6601.1 R6601.2 | length 61.3
  Bottom w12: CON6601.1@2160.7,810.83 2160.95,810.83 C6601.1@2160.95,849.83 R6601.2@2182.95,849.83
N17960953: CON2101.3 R2137.1 R2139.2 | length 192.2
  Bottom w4: R2139.2@1363.31,3317.09 1363.31,3375.09 1392.31,3404.09 1418.31,3404.09 1431.95,3417.72 R2137.1@1431.95,3464.61
  Bottom w30: R2137.1@1431.95,3464.61 R2137.1@1431.95,3465.6
N18046092: C2019.1 R2037.2 U2001.T11 | length 209.6
  Top w4: R2037.2@650.54,3111.83 650.54,3114.09 v1(653.31,3114.09) ; v1(716.31,3107.09) 719.31,3107.09 C2019.1@724.31,3102.09 ; C2019.1@722.31,3098.59 722.31,3097.09 721.56,3097.84 C2019.1@722.31,3098.59 ; C2019.1@722.31,3098.59 725.06,3101.34 724.31,3101.34 C2019.1@724.31,3102.09 ; C2019.1@722.31,3098.59 722.31,3102.09 C2019.1@724.31,3102.09
  Top w8: C2019.1@724.31,3102.09 837.47,3102.09 U2001.T11@836.84,3101.46
  Inner Layer 2 w12: v1(653.31,3114.09) 695.93,3114.09 702.93,3107.09 v1(716.31,3107.09)
N18046094: C2016.1 R2036.2 U2001.K1 | length 258.2
  Top w4: U2001.K1@931.33,3258.94 931.58,3258.94 U2001.K1@932.31,3259.68
  Top w8: C2016.1@901.95,3354.83 901.95,3352.18 918.95,3352.18 932.31,3338.82 U2001.K1@932.31,3259.68
  Top w12: R2036.2@847.95,3469.9 849.95,3469.9 868.95,3450.9 868.95,3386.83 869.95,3386.83 C2016.1@901.95,3354.83
N18046114: C2017.1 R2099.2 U2001.T8 | length 262.9
  Top w4: C2017.1@675.31,3183.09 C2017.1@675.31,3185.09 677.05,3186.83 v1(682.95,3186.83)
  Top w8: 817.95,3152.83 822.08,3148.7 U2001.T8@836.84,3148.7
  Top w10: v1(732.95,3190.83) 749.38,3190.83 783.38,3156.83 813.95,3156.83 817.95,3152.83
  Top w12: R2099.2@610.54,3217.83 610.54,3215.83 641.28,3185.09 C2017.1@675.31,3185.09
  Inner Layer 2 w12: v1(682.95,3186.83) 686.95,3190.83 v1(732.95,3190.83)
N18046118: C2018.1 R2098.2 U2001.T13 | length 175.1
  Top w8: C2018.1@761.95,3045.83 761.95,3047.09 773.33,3047.09 794.33,3068.09 834.97,3068.09 U2001.T13@836.84,3069.96
  Top w10: R2098.2@688.9,3033.83 689.54,3025.83 739.03,3025.83 760.49,3047.29 761.95,3047.29 C2018.1@761.95,3047.09
N18047216: C2020.1 R2047.2 U2001.M2 | length 297.4
  Top w8: C2020.1@848.95,3396.49 848.95,3386.83 881.95,3353.83 881.95,3316.88 882.95,3315.88 882.95,3299.17 912.31,3269.81 912.31,3252.79 902.71,3243.19 U2001.M2@899.83,3243.19
  Top w12: R2047.2@796.31,3468.5 796.31,3477.09 828.95,3444.45 828.95,3416.49 C2020.1@848.95,3396.49
N18144801: C2403.1 R2405.2 U2402.A2 | length 74.9
  Top w12: C2403.1@1396.31,2860.09 1398.06,2858.34 U2402.A2@1438.44,2858.34
  Top w20: C2403.1@1396.31,2860.09 R2405.2@1396.31,2892.09
N18144815: R2404.2 U2402.B2 | length 89.2
  Top w4: R2404.2@1378.31,2931.09 1392.31,2917.09 1404.8,2917.09 1420.31,2901.57 1420.31,2892.22 U2402.B2@1438.44,2874.09
N18144862: R2407.2 U2402.A1 | length 41.2
  Top w4: U2402.A1@1454.19,2858.34 1469.57,2858.34 1484.31,2873.09 R2407.2@1489.31,2873.09
N18144873: L2402.1 U2402.B1 | length 96.8
  Top w10: U2402.B1@1454.19,2874.09 1464.36,2874.09 1518.89,2928.62 L2402.1@1518.89,2938.09
N18144932: R2403.2 U2401.5 | length 26.4
  Bottom w4: U2401.5@821.98,3563.64 835.87,3563.64 836.34,3564.11 R2403.2@848.2,3564.11
N18144946: C2402.1 R2408.2 U2401.7 U2401.8 | length 129.6
  Bottom w15: C2402.1@792.31,3467.09 818.31,3467.09 ; U2401.7@821.98,3524.27 U2401.8@821.98,3504.58 821.98,3470.75 818.31,3467.09 ; R2408.2@859.31,3475.09 859.31,3474.09 852.31,3467.09 818.31,3467.09
N18144981: R2406.2 U2401.6 | length 25.6
  Bottom w4: U2401.6@821.98,3543.95 836.09,3543.95 836.93,3543.11 R2406.2@847.2,3543.11
N18263809: C3334.1 R3327.1 R3334.2 | length 766.4
  Top w5: v1(1770.65,3392.59) 1769.77,3393.47 cw(c1774.9,3398.59) 1767.65,3398.59 1767.65,3671.59 cw(c1794.21,3671.59) C3334.1@1775.42,3690.36 ; C3334.1@1775.43,3690.37 C3334.1@1780.65,3695.59 ; R3334.2@2143.65,3400.59 R3327.1@2143.65,3375.59 2145.84,3375.59 v1(2145.84,3369.73)
  Inner Layer 2 w3: v1(1770.65,3392.59) 1770.65,3380.59 v3(1773.65,3377.59) ; v3(2143.65,3354.59) 2144.75,3354.59 2144.75,3369.73 v1(2145.84,3369.73)
  Inner Layer 5 w3: v3(1773.65,3377.59) 1779.46,3383.4 cw(c1801.65,3361.21) 1801.65,3392.59 1813.65,3392.59 cw(c1813.65,3365.96) 1832.48,3384.79 1858.92,3358.35 ccw(c1877.65,3377.08) 1877.65,3350.59 2139.65,3350.59 v3(2143.65,3354.59)
N18274814: CON6505.2 R6508.2 R6509.2 R6510.2 | length 129.8
  Top w4: CON6505.2@147.48,4483.76 148.55,4484.83 206.31,4484.83 206.31,4485.5 207.91,4485.49 210.31,4483.09 231.31,4483.09 R6510.2@232.31,4482.09 233.31,4483.09 R6508.2@254.31,4483.09 R6509.2@274.31,4483.09
N18389140: R3704.1 U3701.G2 | length 113
  Top w4: U3701.G2@1847.69,4558.21 1847.69,4573.65 1862.13,4588.09 1892.31,4588.09 1912.95,4608.72 R3704.1@1912.95,4626.49
N18389142: R3714.1 R3716.1 R3718.2 U3701.J3 | length 176.7
  Top w6: R3714.1@1715.46,4610.49 R3714.1@1717.95,4610.49
  Top w12: R3716.1@1716.95,4557.49 1716.95,4572.49 ; R3714.1@1717.95,4610.49 R3718.2@1717.95,4589.49 1716.95,4588.49 1716.95,4572.49 ; v1(1730.6,4573.51) 1717.95,4573.49 1716.95,4572.49
  Inner Layer 2 w6: v1(1730.6,4573.51) 1742.76,4573.51 1752.73,4583.49 1775.17,4583.49 v4(1816.19,4542.46)
N18389271: NTC3701.1 U3701.C10 | length 205.6
  Top w4: U3701.C10@1910.68,4432.22 1910.68,4428.74 1938.34,4401.09 v1(1941.31,4401.09)
  Inner Layer 2 w4: v1(1941.31,4401.09) 1949.31,4409.09 2009.31,4409.09 2011.81,4406.59 v3(2011.31,4411.09)
  Inner Layer 5 w4: v2(2010.31,4467.09) 2016.31,4461.09 2016.31,4416.09 v3(2011.31,4411.09)
  Bottom w4: v2(2010.31,4467.09) 2019.32,4467.35 NTC3701.1@2020.08,4468.11 2019.87,4468.11 2019.32,4467.56 v2(2010.31,4467.09)
N18389436: U3701.J1 X3701.3 | length 85.3
  Top w4: U3701.J1@1816.19,4573.96 1821.31,4579.07 1821.31,4598.82 1857.45,4634.95 X3701.3@1857.45,4642.18
N18389478: R3712.1 R3717.1 R3719.2 U3701.J5 | length 135.2
  Top w4: R3719.2@1717.95,4492.49 1717.95,4494.99 1738.7,4515.74 R3717.1@1737.95,4516.49 ; R3712.1@1737.95,4537.49 R3717.1@1737.95,4516.49 ; v1(1738.95,4516.49) R3717.1@1737.95,4516.49
  Inner Layer 2 w4: v1(1738.95,4516.49) 1745.35,4510.09 1786.3,4510.09 1787.18,4510.96 v4(1816.19,4510.96)
N18389786: R3732.1 U3701.J4 | length 62.8
  Top w4: v1(1760.31,4522.09) R3732.1@1758.95,4523.49 1759.53,4524.07 R3732.1@1760.35,4524.07 ; v4(1816.19,4526.71) 1816.2,4526.98 v4(1816.19,4526.71)
  Inner Layer 2 w4: v1(1760.31,4522.09) 1809.5,4522.09 1815.16,4527.74 v4(1816.19,4526.71)
N18393681: C3911.1 C3912.1 R3909.2 U3901.C3 | length 28.9
  Top w4: C3911.1@1774.31,2739.56 1774.31,2741.82 C3911.1@1774.57,2742.08 ; U3901.C3@1854.45,2793.19 U3901.C3@1854.93,2793.19
  Top w8: U3901.C3@1854.32,2792.58 U3901.C3@1854.93,2793.19
  Top w12: 1837.08,2775.58 1854.57,2793.07 U3901.C3@1854.45,2793.19
N18394314: C3913.1 R3907.2 U3901.B1 | length 52.3
  Top w4: C3913.1@1851.95,2854.96 R3907.2@1870.68,2854.96 ; U3901.B1@1870.68,2824.69 R3907.2@1870.68,2854.96 ; R3907.2@1873.95,2854.96 R3907.2@1870.68,2854.96
N18394330: PL3901.1 U3901.B3 | length 69.3
  Top w8: 1862.31,2774.56 1870.68,2782.93 U3901.B3@1870.68,2793.19
  Top w12: PL3901.1@1840.12,2736.56 1840.12,2752.36 1862.31,2774.56
N18394364: PA3901.8 R3903.1 | length 50.3
  Bottom w4: R3903.1@1914.31,4418.09 1921.23,4418.09 1945.08,4394.24 1945.08,4386.33 PA3901.8@1943.31,4386.34
N18485345: C4001.1 CON4001.4 R4001.1 | length 87.1
  Top w10: CON4001.4@601.19,1204.8 653.26,1204.8 C4001.1@653.95,1205.49 653.95,1237.49 R4001.1@655.95,1237.49
N18693233: C2320.1 PL2305.1 R2316.2 U2301.B3 | length 188.8
  Bottom w10: PL2305.1@141.83,3647.09 141.83,3618.21 164.95,3595.09 U2301.B3@164.95,3581.19
  Bottom w12: PL2305.1@141.83,3647.09 150.31,3647.09 150.31,3694.85 C2320.1@165.95,3710.49
  Bottom w15: C2320.1@165.95,3710.49 165.95,3744.49 R2316.2@166.95,3744.49
N19383884: C6205.1 CON6202.4 R6206.1 | length 452.4
  Top w4: CON6202.4@1870.44,5051.05 1870.44,5059.96 1870.31,5060.09 CON6202.4@1870.44,5053.06
  Top w8: v1(1870.31,4998.09) 1870.44,4998.21 CON6202.4@1870.44,5051.05
  Top w12: R6206.1@1582.31,4887.09 1583.31,4887.09 1573.31,4897.09 C6205.1@1573.31,4915.09 v1(1606.31,4915.09)
  Inner Layer 2 w12: v1(1606.31,4915.09) 1606.31,4916.59 1623.31,4916.59 1623.31,4918.09 v3(1625.95,4918.83) 1623.31,4918.83 1623.31,4939.09 1639.31,4955.09 1802.51,4955.09 1835.51,4988.09 1860.31,4988.09 v1(1870.31,4998.09)
N19385665: L2401.1 U2401.2 | length 45.3
  Bottom w12: L2401.1@706.68,3525.11 706.68,3524.27 U2401.2@751.11,3524.27
N19387299: C2413.2 R2416.1 R2417.2 U2401.4 | length 101.7
  Bottom w4: U2401.4@747.17,3563.64 U2401.4@751.11,3563.64 U2401.4@747.17,3563.64
  Bottom w12: C2413.2@684.31,3589.09 709.31,3589.09 R2416.1@705.8,3589.2 715.92,3589.2 716.04,3589.09 R2417.2@728.31,3589.09 741.66,3589.09 751.11,3579.64 U2401.4@751.11,3563.64
N19622553: C2054.1 R2043.2 U2001.N3 | length 132.9
  Inner Layer 2 w4: v3(880.31,3244.09) 884.08,3240.32 v4(884.09,3227.44)
  Inner Layer 5 w4: v3(880.31,3244.09) 894.46,3258.23 v2(908.48,3258.23)
  Bottom w4: v2(908.48,3258.23) 928.31,3278.07 C2054.1@928.31,3293.09 928.31,3321.85 930.95,3324.49 928.95,3326.49 R2043.2@930.95,3325.49
N19636347: R2005.2 SH2014.2 | length 37.2
  Top w12: SH2014.2@1049.58,2855.15 1049.58,2862.78 1065.81,2879.01 R2005.2@1065.81,2885.65
N19636459: C2043.1 R2005.1 U2001.C15 | length 155.3
  Top w4: C2043.1@1045.81,2910.65 1045.96,2910.65 v1(1045.96,2914.21)
  Top w12: R2005.1@1045.81,2885.65 C2043.1@1045.81,2910.65
  Inner Layer 2 w10: v4(1041.57,3038.47) 1041.56,3011.83 1040.95,3011.22 1040.95,2930.65 1045.96,2925.64 v1(1045.96,2914.21)
N19717773: ANT3611.2 L3601.1 L3606.2 R3602.2 R3607.1 R3608.1 TP3601.1 | length 2444
  Top w4: TP3601.1@256.3,250.09 256.3,298.09 v5(256.3,306.09)
  Top w5: v5(1332.3,95.09) v5(1368.3,59.09) ; v5(1368.3,95.09) v5(1368.3,59.09) ; v5(1404.3,59.09) v5(1368.3,59.09) ; v5(1404.3,95.09) v5(1368.3,59.09)
  Top w40: 256.3,34.09 TP3601.1@256.3,250.09 ; 257.3,24.09 865.3,24.09 ; 263.3,116.09 1407.3,116.09
  Inner Layer 2 w4: v5(256.3,306.09) v5@257.3,306.09
  Bottom w4: L3601.1@274.05,393 L3601.1@274.3,391.09
  Bottom w5: R3602.2@198.95,428.49 234.3,393.14 R3607.1@234.3,391.09 256.3,391.09 ; 256.3,363.09 256.3,391.09 ; L3606.2@314.95,428.49 311.7,428.49 L3601.1@274.3,391.09 256.3,391.09 ; ANT3611.2@1368.21,69.11 1368.3,69.11 v5(1368.3,59.09)
  Bottom w20: v5(256.3,306.09) 256.3,363.09
  other v5: 1332.3,23.09 1368.3,23.09 1404.3,23.09 1332.3,59.09
N19732623: L3603.1 TP3602.1 | length 464.3
  Top w4: v5(158.3,306.09) 159.3,306.09 159.3,298.09 TP3602.1@159.3,251.09
  Top w40: 56.3,130.09 ccw(c185.61,156.4) 159.3,27.09 TP3602.1@159.3,251.09
  Bottom w4: v5(158.3,306.09) v5@158.3,310.09
  Bottom w20: v5@158.3,310.09 L3603.1@158.3,336.09
N19732657: R3601.1 TP3603.1 | length 202
  Top w4: TP3603.1@365.3,250.09 366.3,250.09 366.3,298.09 v5(366.3,306.09)
  Top w40: 366.3,135.09 TP3603.1@366.3,250.09
  Bottom w20: v5(366.3,306.09) R3601.1@366.3,336.09
N19732800: ANT3606.1 ANT3606.2 R3605.1 | length 201
  Bottom w20: R3605.1@2188.3,4866.09 ANT3606.2@2324.31,4866.09 ; ANT3606.2@2324.31,4845.13 ANT3606.2@2324.31,4866.09 ; ANT3606.1@2324.31,4910.09 ANT3606.2@2324.31,4866.09
N19780807: L3606.1 U3601.1 | length 33.5
  Bottom w5: U3601.1@281.43,464.44 295.14,464.44 295.18,464.49 L3606.1@314.95,464.49
N19781365: R3617.1 R3626.1 R3627.1 U3603.2 | length 293
  Bottom w4: R3626.1@114.95,762.49 78.31,725.85 78.31,653.09 112.44,618.96 U3603.2@166.56,618.96
  Bottom w6: R3626.1@114.95,762.49 R3627.1@114.95,795.49 R3617.1@114.95,828.49
N19784470: R2039.2 U2001.H3 U2001.J2 | length 168.7
  Top w4: U2001.J2@947.08,3243.19 U2001.J2@947.08,3243.19 v4(962.83,3227.44) v4(962.83,3227.44) ; R2039.2@968.95,3342.83 968.87,3341.83 R2039.2@968.95,3341.83 ; R2039.2@970.95,3339.83 R2039.2@968.95,3341.83 ; v1(972.55,3331.83) 972.55,3341.83 R2039.2@968.95,3341.83 ; R2039.2@968.86,3341.8 961.95,3339.83 968.95,3339.83 R2039.2@968.95,3341.64 ; R2039.2@968.86,3341.8 968.86,3341.74 R2039.2@968.95,3341.64 ; R2039.2@968.86,3341.8 R2039.2@968.95,3341.83 ; R2039.2@968.95,3341.64 R2039.2@968.95,3341.83
  Inner Layer 2 w10: v4(962.83,3227.44) 962.82,3251.34 977.31,3265.83 977.31,3327.06 v1(972.55,3331.83)
N19786985: L3608.1 U3602.1 | length 33
  Bottom w5: U3602.1@2135.24,4738.09 2135.24,4751.52 2135.3,4751.59 L3608.1@2135.3,4771.09
N19787376: R3606.1 U3602.7 | length 31
  Bottom w5: U3602.7@2135.24,4688.09 2135.24,4675.65 2135.3,4675.59 R3606.1@2135.3,4657.09
N19787407: R3615.2 U3602.8 | length 47.7
  Bottom w5: R3615.2@2091.3,4722.09 2100.3,4713.09 U3602.8@2135.24,4713.09
N19787517: R3616.2 R3628.1 R3629.1 U3602.3 | length 316.2
  Inner Layer 2 w4: v3(2016.3,4818.09) 2083.3,4818.09 2156.34,4745.05 v3(2156.97,4745.68)
  Inner Layer 5 w4: v2(1976.3,4753.09) 1976.3,4778.09 v3(2016.3,4818.09) ; v3(2156.97,4745.68) 2160.71,4745.68 v2(2177.3,4729.09)
  Bottom w4: v2(2177.3,4729.09) 2177.3,4738.02 U3602.3@2177.37,4738.09 ; R3616.2@1974.3,4753.09 v2(1976.3,4753.09) 1975.3,4754.09 R3616.2@1974.3,4753.09 ; R3616.2@1974.3,4753.09 1972.3,4753.09 R3616.2@1966.3,4747.09 1967.3,4747.09 1967.3,4746.09 R3616.2@1974.3,4753.09
N19789349: L3607.1 L3611.1 R3604.2 R3612.2 R3615.1 | length 198.6
  Bottom w5: R3615.1@2091.3,4686.09 L3611.1@2091.3,4654.09 R3612.2@2091.3,4620.09 2091.3,4595.09 2115.3,4571.09 R3604.2@2155.3,4571.09 2183.29,4571.09 L3607.1@2187.29,4567.09
N19789585: R3619.1 R3630.1 R3631.1 U3604.2 | length 119.4
  Bottom w4: R3630.1@1930.3,4677.09 1934.3,4677.09 R3619.1@1966.3,4645.09 R3619.1@1966.3,4638.34 ; R3631.1@1966.3,4614.09 R3619.1@1966.3,4638.34 ; U3604.2@2005.43,4638.34 R3619.1@1966.3,4638.34
N19790693: R3602.1 U3601.7 | length 32.5
  Bottom w5: R3602.1@198.95,464.49 218.2,464.49 218.24,464.44 U3601.7@231.43,464.44
N19790880: R3610.2 U3601.8 | length 33.3
  Bottom w5: U3601.8@256.43,464.44 256.43,496.97 R3610.2@256.95,497.49
N19790902: L3605.1 L3609.1 R3603.2 R3609.2 R3610.1 | length 106.2
  Bottom w5: L3609.1@224.31,571.09 R3603.2@257.31,571.09 ; R3609.2@256.95,533.49 257.31,533.85 R3603.2@257.31,571.09 ; L3605.1@292.31,570.09 291.31,571.09 R3603.2@257.31,571.09
N19790954: R3613.2 R3624.1 R3625.1 U3601.3 | length 349.7
  Inner Layer 2 w4: v3(143.3,661.09) 193.31,661.09 223.31,631.09 223.31,496.08 280.3,439.09 v3(281.85,439.05)
  Inner Layer 5 w4: v2(141.9,679.14) 142.6,679.14 142.6,661.09 v3(143.3,661.09) ; v2(281.22,422.35) 281.22,432.01 283.3,434.09 280.73,438.38 v3(281.85,439.05)
  Bottom w4: v2(141.9,679.14) v2(141.9,679.14) R3613.2@143.3,679.09 ; v2(281.22,422.35) 281.28,422.24 281.3,422.19 281.34,422.23 U3601.3@281.43,422.32
N19794660: CON6503.2 R6507.2 | length 86.8
  Bottom w4: CON6503.2@2014.37,4987.91 2014.37,4947.21 2014.31,4947.16 2014.31,4932.07 2016.36,4930.03 ; 2016.36,4929.49 2016.36,4930.03 ; R6507.2@2041.3,4930.09 2039.49,4931.89 2016.36,4931.89 2016.36,4930.03
N19796015: CON2101.2 R2103.1 R2105.1 VR2102.1 | length 622.3
  Top w4: R2103.1@729.95,3403.83 734.95,3403.83 738.69,3400.09 v1(756.47,3400.09) 755.93,3399.55 764.85,3390.63 764.31,3390.63 764.31,3390.09 R2105.1@765.31,3390.09
  Inner Layer 2 w4: v1(756.47,3400.09) 756.47,3397.09 781.85,3397.09 792.85,3386.09 834.26,3386.09 846.66,3373.69 855.92,3373.69 v3(857.16,3372.1)
  Inner Layer 5 w4: v3(857.16,3372.1) 880.54,3372.1 885.53,3377.09 929.3,3377.09 1019.3,3467.09 1088.13,3467.09 1125.13,3504.09 1142.31,3504.09 1152.31,3514.09 v2(1168.31,3514.09)
  Bottom w4: VR2102.1@1166.95,3544.08 v2@1166.95,3515.59 ; v2(1168.31,3514.09) 1168.31,3515.59 v2@1166.95,3515.59 ; CON2101.2@1177.31,3456.21 1169.38,3465.6 1166.95,3468.03 v2@1166.95,3515.59
N19804026: ANT3611.1 R3618.1 | length 117.4
  Bottom w20: ANT3611.1@383.96,69.11 389.3,29.09 R3618.1@466.3,29.09
N19868309: C3916.1 R3908.2 U3901.A1 | length 57.1
  Top w4: U3901.A1@1886.43,2824.69 1886.43,2844.43 R3908.2@1897.95,2855.96 1899.08,2857.09 C3916.1@1899.08,2876.58
N19974105: U3701.K1 X3701.1 | length 176.1
  Top w4: X3701.1@1794.46,4728.8 1794.45,4723.87 1823.09,4695.23 1823.09,4612.02 1811.22,4600.15 1811.22,4584.73 U3701.K1@1800.45,4573.96
N19975328: R3910.1 R3911.2 U3901.B2 | length 163.7
  Top w4: R3910.1@1808.31,2735.56 1808.31,2735.31 v1(1811.69,2735.31)
  Top w10: R3911.2@1763.08,2712.58 1780.06,2712.58 1803.04,2735.56 R3910.1@1808.31,2735.56
  Inner Layer 2 w8: v1(1811.69,2735.31) 1824.05,2735.31 1870.68,2781.95 v4(1870.68,2808.94)
N20607847: R3818.1 U3801.8 | length 76.2
  Top w4: R3818.1@2031.45,4527.99 2043.95,4540.49 2043.95,4575.51 2054.53,4586.09 U3801.8@2063.06,4586.09
N20607950: R3819.1 U3801.5 | length 34.2
  Top w5: U3801.5@2078.81,4633.33 2078.81,4662.58 R3819.1@2082.31,4666.09
N21349565: D6301.2 Q6302.3 | length 266.8
  Top w6: Q6302.3@661.45,4768.13 662.44,4768.13 678.41,4784.1 682.22,4784.1 712.95,4814.83 712.95,4983.93 D6301.2@693.96,5002.92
